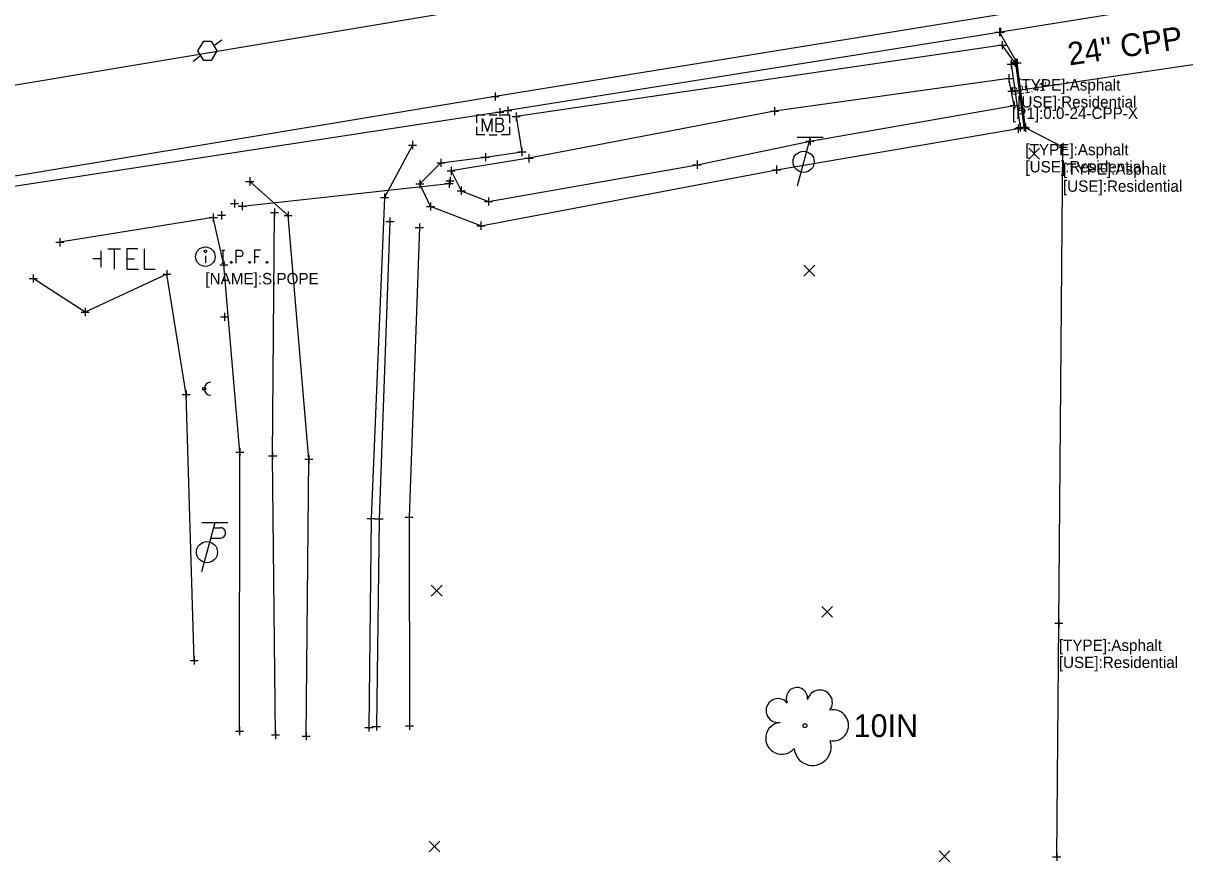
# Model space of a CAD drawing. Extents: x 1386013 to 1389776, y 604170 to 607009.
# Drawn here: x 1386419.5 to 1386562.3, y 604550 to 604653.1 of the extents above; entities that cross this region are included whole.
import ezdxf

# ---------------------------------------------------------------- set-up
doc = ezdxf.new("R2010")
doc.units = 0
for name, color, linetype in [('_CIVIL_CONSTRUCTION', 7, 'Continuous'), ('Default', 7, 'Continuous'), ('DR_X_Ditch', 7, 'Continuous'), ('DR_X_Elev_Flow', 7, 'Continuous'), ('DR_X_Headwall', 7, 'Continuous'), ('DR_X_Storm_Sewer', 7, 'Continuous'), ('DR_X_Text', 7, 'Continuous'), ('DV_X_Text', 7, 'Continuous'), ('PV_X_COP', 7, 'Continuous'), ('PV_X_Driveway', 7, 'Continuous'), ('PV_X_EOP', 7, 'Continuous'), ('PV_X_Shoulder', 7, 'Continuous'), ('RD_X_Cells', 7, 'Continuous'), ('RW_P_Esmt_SH', 7, 'Continuous'), ('SC_Scratch1', 7, 'Continuous'), ('SV_P_Mon_Cells_Set', 7, 'Continuous'), ('SV_X_Mon_Cells_Found_Text', 7, 'Continuous'), ('SV_X_Random_Point', 7, 'Continuous'), ('SV_X_Text', 7, 'Continuous'), ('SV_X_Toe_of_Slope', 7, 'Continuous'), ('SV_X_Top_of_Bank', 7, 'Continuous'), ('UT_X_Telecom_Cells', 7, 'Continuous'), ('VG_X_Text', 7, 'Continuous')]:
    doc.layers.add(name, color=color, linetype=linetype)

msp = doc.modelspace()

# ---------------------------------------------------------------- linework, layer by layer
at = {"layer": '_CIVIL_CONSTRUCTION'}
msp.add_circle((1386515.61, 604566.7), 0.24, dxfattribs=at)
for centre, radius, start, end in [((1386514.63, 604570.07), 1.32, 354.0047, 205.9741), ((1386517.44, 604569.53), 1.55, 323.83, 165.0376), ((1386512.3, 604568.56), 1.47, 39.0625, 279.5412), ((1386519.07, 604566.74), 1.91, 259.1453, 101.4596), ((1386512.76, 604565.15), 1.97, 96.1722, 320.5737), ((1386516.56, 604564.09), 2.28, 184.9476, 19.4572)]:
    msp.add_arc(centre, radius, start, end, dxfattribs=at)
at = {"layer": 'Default'}
msp.add_lwpolyline([(1386446.4, 604630.59), (1386471.84, 604633.36)], dxfattribs=at)
at = {"layer": 'DR_X_Ditch'}
msp.add_lwpolyline([(1386446.07, 604566.04), (1386446.11, 604600.33), (1386444.14, 604623.38), (1386442.84, 604629.19), (1386423.97, 604626.15)], dxfattribs=at)
at = {"layer": 'DR_X_Elev_Flow'}
for p, q in [((1386471.46, 604633.71), (1386472.46, 604633.71)), ((1386471.96, 604634.21), (1386471.96, 604633.21)), ((1386471.96, 604633.71), (1386471.96, 604633.71)), ((1386444.95, 604630.92), (1386445.95, 604630.92)), ((1386445.45, 604631.42), (1386445.45, 604630.42)), ((1386445.45, 604630.92), (1386445.45, 604630.92)), ((1386443.36, 604629.47), (1386444.36, 604629.47)), ((1386443.86, 604629.97), (1386443.86, 604628.97)), ((1386443.86, 604629.47), (1386443.86, 604629.47)), ((1386443.72, 604616.97), (1386444.72, 604616.97)), ((1386444.22, 604617.47), (1386444.22, 604616.47)), ((1386444.22, 604616.97), (1386444.22, 604616.97))]:
    msp.add_line(p, q, dxfattribs=at)
at = {"layer": 'DR_X_Headwall'}
msp.add_lwpolyline([(1386541.55, 604648.22), (1386540.98, 604648.07), (1386542.07, 604640.28), (1386542.59, 604640.31)], close=True, dxfattribs=at)
at = {"layer": 'DR_X_Storm_Sewer'}
for q in [(1386569.43, 604648.91), (1386541.08, 604644.72)]:
    msp.add_line((1386541.08, 604644.72), q, dxfattribs=at)
at = {"layer": 'DV_X_Text'}
for p, q in [((1386539.06, 604652.01), (1386540.06, 604652.01)), ((1386539.17, 604652.01), (1386540.17, 604652.01)), ((1386539.56, 604652.51), (1386539.56, 604651.51)), ((1386539.56, 604652.01), (1386539.56, 604652.01)), ((1386539.67, 604652.51), (1386539.67, 604651.51)), ((1386539.67, 604652.01), (1386539.67, 604652.01)), ((1386539.86, 604650.89), (1386539.86, 604649.89)), ((1386539.36, 604650.39), (1386540.36, 604650.39)), ((1386539.86, 604650.39), (1386539.86, 604650.39)), ((1386540.48, 604648.07), (1386541.48, 604648.07)), ((1386540.91, 604648.25), (1386541.91, 604648.25)), ((1386540.98, 604648.57), (1386540.98, 604647.57)), ((1386540.98, 604648.07), (1386540.98, 604648.07)), ((1386541.05, 604648.22), (1386542.05, 604648.22)), ((1386541.22, 604648.21), (1386542.22, 604648.21)), ((1386541.41, 604648.75), (1386541.41, 604647.75)), ((1386541.41, 604648.25), (1386541.41, 604648.25)), ((1386541.55, 604648.72), (1386541.55, 604647.72)), ((1386541.55, 604648.22), (1386541.55, 604648.22)), ((1386541.72, 604648.71), (1386541.72, 604647.71)), ((1386541.72, 604648.21), (1386541.72, 604648.21)), ((1386540.21, 604646.31), (1386541.21, 604646.31)), ((1386540.71, 604646.81), (1386540.71, 604645.81)), ((1386540.71, 604646.31), (1386540.71, 604646.31)), ((1386541.08, 604645.22), (1386541.08, 604644.22)), ((1386477.01, 604644.07), (1386478.01, 604644.07)), ((1386477.51, 604644.57), (1386477.51, 604643.57)), ((1386477.51, 604644.07), (1386477.51, 604644.07)), ((1386540.58, 604644.72), (1386541.58, 604644.72)), ((1386541.08, 604644.72), (1386541.08, 604644.72)), ((1386541.34, 604643.46), (1386541.34, 604642.46)), ((1386477.57, 604642.14), (1386478.57, 604642.14)), ((1386478.07, 604642.64), (1386478.07, 604641.64)), ((1386478.07, 604642.14), (1386478.07, 604642.14)), ((1386478.58, 604642.34), (1386479.58, 604642.34)), ((1386479.08, 604642.84), (1386479.08, 604641.84)), ((1386479.08, 604642.34), (1386479.08, 604642.34)), ((1386480.09, 604642.1), (1386480.09, 604641.1)), ((1386511.36, 604642.27), (1386512.36, 604642.27)), ((1386511.86, 604642.77), (1386511.86, 604641.77)), ((1386511.86, 604642.27), (1386511.86, 604642.27)), ((1386540.84, 604642.96), (1386541.84, 604642.96)), ((1386541.34, 604642.96), (1386541.34, 604642.96)), ((1386479.59, 604641.6), (1386480.59, 604641.6)), ((1386480.09, 604641.6), (1386480.09, 604641.6)), ((1386541.86, 604640.63), (1386541.86, 604639.63)), ((1386542.07, 604640.78), (1386542.07, 604639.78)), ((1386542.59, 604640.81), (1386542.59, 604639.81)), ((1386542.73, 604640.74), (1386542.73, 604639.74)), ((1386516.24, 604639.08), (1386516.24, 604638.08)), ((1386541.36, 604640.13), (1386542.36, 604640.13)), ((1386541.57, 604640.28), (1386542.57, 604640.28)), ((1386541.86, 604640.13), (1386541.86, 604640.13)), ((1386542.07, 604640.28), (1386542.07, 604640.28)), ((1386542.09, 604640.31), (1386543.09, 604640.31)), ((1386542.23, 604640.24), (1386543.23, 604640.24)), ((1386542.59, 604640.31), (1386542.59, 604640.31)), ((1386542.73, 604640.24), (1386542.73, 604640.24)), ((1386466.85, 604638.11), (1386467.85, 604638.11)), ((1386467.35, 604638.61), (1386467.35, 604637.61)), ((1386467.35, 604638.11), (1386467.35, 604638.11)), ((1386480.81, 604637.76), (1386480.81, 604636.76)), ((1386515.74, 604638.58), (1386516.74, 604638.58)), ((1386516.24, 604638.58), (1386516.24, 604638.58)), ((1386546.85, 604637.86), (1386547.85, 604637.86)), ((1386547.35, 604638.36), (1386547.35, 604637.36)), ((1386547.35, 604637.86), (1386547.35, 604637.86)), ((1386470.84, 604636.42), (1386470.84, 604635.42)), ((1386475.81, 604636.61), (1386476.81, 604636.61)), ((1386476.31, 604637.11), (1386476.31, 604636.11)), ((1386476.31, 604636.61), (1386476.31, 604636.61)), ((1386480.31, 604637.26), (1386481.31, 604637.26)), ((1386480.81, 604637.26), (1386480.81, 604637.26)), ((1386481.17, 604636.48), (1386482.17, 604636.48)), ((1386481.67, 604636.98), (1386481.67, 604635.98)), ((1386481.67, 604636.48), (1386481.67, 604636.48)), ((1386502.34, 604636.19), (1386502.34, 604635.19)), ((1386470.34, 604635.92), (1386471.34, 604635.92)), ((1386470.84, 604635.92), (1386470.84, 604635.92)), ((1386471.6, 604634.92), (1386472.6, 604634.92)), ((1386472.1, 604635.42), (1386472.1, 604634.42)), ((1386472.1, 604634.92), (1386472.1, 604634.92)), ((1386501.84, 604635.69), (1386502.84, 604635.69)), ((1386502.34, 604635.69), (1386502.34, 604635.69)), ((1386511.63, 604635.08), (1386512.63, 604635.08)), ((1386512.13, 604635.58), (1386512.13, 604634.58)), ((1386512.13, 604635.08), (1386512.13, 604635.08)), ((1386446.82, 604633.64), (1386447.82, 604633.64)), ((1386447.32, 604634.14), (1386447.32, 604633.14)), ((1386447.32, 604633.64), (1386447.32, 604633.64)), ((1386467.75, 604633.32), (1386468.75, 604633.32)), ((1386468.25, 604633.82), (1386468.25, 604632.82)), ((1386468.25, 604633.32), (1386468.25, 604633.32)), ((1386471.34, 604633.36), (1386472.34, 604633.36)), ((1386471.84, 604633.86), (1386471.84, 604632.86)), ((1386471.84, 604633.36), (1386471.84, 604633.36)), ((1386463.89, 604632.16), (1386463.89, 604631.16)), ((1386472.85, 604632.49), (1386473.85, 604632.49)), ((1386473.35, 604632.99), (1386473.35, 604631.99)), ((1386473.35, 604632.49), (1386473.35, 604632.49)), ((1386445.9, 604630.59), (1386446.9, 604630.59)), ((1386446.4, 604631.09), (1386446.4, 604630.09)), ((1386446.4, 604630.59), (1386446.4, 604630.59)), ((1386463.39, 604631.66), (1386464.39, 604631.66)), ((1386463.89, 604631.66), (1386463.89, 604631.66)), ((1386469.07, 604630.56), (1386470.07, 604630.56)), ((1386469.57, 604631.06), (1386469.57, 604630.06)), ((1386469.57, 604630.56), (1386469.57, 604630.56)), ((1386476.18, 604631.17), (1386477.18, 604631.17)), ((1386476.68, 604631.67), (1386476.68, 604630.67)), ((1386476.68, 604631.17), (1386476.68, 604631.17)), ((1386442.34, 604629.19), (1386443.34, 604629.19)), ((1386442.84, 604629.69), (1386442.84, 604628.69)), ((1386442.84, 604629.19), (1386442.84, 604629.19)), ((1386449.88, 604629.82), (1386450.88, 604629.82)), ((1386450.38, 604630.32), (1386450.38, 604629.32)), ((1386450.38, 604629.82), (1386450.38, 604629.82)), ((1386451.55, 604629.43), (1386452.55, 604629.43)), ((1386452.05, 604629.93), (1386452.05, 604628.93)), ((1386452.05, 604629.43), (1386452.05, 604629.43)), ((1386464.57, 604629.2), (1386464.57, 604628.2)), ((1386464.07, 604628.7), (1386465.07, 604628.7)), ((1386464.57, 604628.7), (1386464.57, 604628.7)), ((1386467.69, 604627.97), (1386468.69, 604627.97)), ((1386468.19, 604628.47), (1386468.19, 604627.47)), ((1386468.19, 604627.97), (1386468.19, 604627.97)), ((1386475.24, 604628.19), (1386476.24, 604628.19)), ((1386475.74, 604628.69), (1386475.74, 604627.69)), ((1386475.74, 604628.19), (1386475.74, 604628.19)), ((1386423.97, 604626.65), (1386423.97, 604625.65)), ((1386423.47, 604626.15), (1386424.47, 604626.15)), ((1386423.97, 604626.15), (1386423.97, 604626.15)), ((1386443.64, 604623.38), (1386444.64, 604623.38)), ((1386444.14, 604623.88), (1386444.14, 604622.88)), ((1386444.14, 604623.38), (1386444.14, 604623.38)), ((1386420.7, 604622.2), (1386420.7, 604621.2)), ((1386436.63, 604622.24), (1386437.63, 604622.24)), ((1386437.13, 604622.74), (1386437.13, 604621.74)), ((1386437.13, 604622.24), (1386437.13, 604622.24)), ((1386420.2, 604621.7), (1386421.2, 604621.7)), ((1386420.7, 604621.7), (1386420.7, 604621.7)), ((1386427.08, 604618.07), (1386427.08, 604617.07)), ((1386426.58, 604617.57), (1386427.58, 604617.57)), ((1386427.08, 604617.57), (1386427.08, 604617.57)), ((1386439.5, 604607.92), (1386439.5, 604606.92)), ((1386439, 604607.42), (1386440, 604607.42)), ((1386439.5, 604607.42), (1386439.5, 604607.42)), ((1386446.11, 604600.83), (1386446.11, 604599.83)), ((1386445.61, 604600.33), (1386446.61, 604600.33)), ((1386446.11, 604600.33), (1386446.11, 604600.33)), ((1386449.64, 604599.89), (1386450.64, 604599.89)), ((1386450.14, 604600.39), (1386450.14, 604599.39)), ((1386450.14, 604599.89), (1386450.14, 604599.89)), ((1386454.09, 604599.46), (1386455.09, 604599.46)), ((1386454.59, 604599.96), (1386454.59, 604598.96)), ((1386454.59, 604599.46), (1386454.59, 604599.46)), ((1386461.76, 604592.18), (1386462.76, 604592.18)), ((1386462.26, 604592.68), (1386462.26, 604591.68)), ((1386462.26, 604592.18), (1386462.26, 604592.18)), ((1386462.74, 604592.13), (1386463.74, 604592.13)), ((1386463.24, 604592.63), (1386463.24, 604591.63)), ((1386463.24, 604592.13), (1386463.24, 604592.13)), ((1386466.43, 604592.36), (1386467.43, 604592.36)), ((1386466.93, 604592.86), (1386466.93, 604591.86)), ((1386466.93, 604592.36), (1386466.93, 604592.36)), ((1386546.34, 604579.29), (1386547.34, 604579.29)), ((1386546.84, 604579.79), (1386546.84, 604578.79)), ((1386546.84, 604579.29), (1386546.84, 604579.29)), ((1386440.49, 604575.23), (1386440.49, 604574.23)), ((1386439.99, 604574.73), (1386440.99, 604574.73)), ((1386440.49, 604574.73), (1386440.49, 604574.73)), ((1386446.07, 604566.54), (1386446.07, 604565.54)), ((1386461.49, 604566.49), (1386462.49, 604566.49)), ((1386461.99, 604566.99), (1386461.99, 604565.99)), ((1386461.99, 604566.49), (1386461.99, 604566.49)), ((1386462.4, 604566.6), (1386463.4, 604566.6)), ((1386462.9, 604567.1), (1386462.9, 604566.1)), ((1386462.9, 604566.6), (1386462.9, 604566.6)), ((1386466.47, 604566.67), (1386467.47, 604566.67)), ((1386466.97, 604567.17), (1386466.97, 604566.17)), ((1386466.97, 604566.67), (1386466.97, 604566.67)), ((1386445.57, 604566.04), (1386446.57, 604566.04)), ((1386446.07, 604566.04), (1386446.07, 604566.04)), ((1386449.99, 604565.56), (1386450.99, 604565.56)), ((1386450.49, 604566.06), (1386450.49, 604565.06)), ((1386450.49, 604565.56), (1386450.49, 604565.56)), ((1386453.77, 604565.4), (1386454.77, 604565.4)), ((1386454.27, 604565.9), (1386454.27, 604564.9)), ((1386454.27, 604565.4), (1386454.27, 604565.4)), ((1386546.08, 604550.58), (1386547.08, 604550.58)), ((1386546.58, 604551.08), (1386546.58, 604550.08)), ((1386546.58, 604550.58), (1386546.58, 604550.58))]:
    msp.add_line(p, q, dxfattribs=at)
at = {"layer": 'PV_X_COP'}
msp.add_lwpolyline([(1387000.37, 604739.9), (1386941.92, 604730.57), (1386886.1, 604721.12), (1386828.75, 604712.1), (1386771.72, 604702.67), (1386713.85, 604693.61), (1386656.33, 604684.46), (1386594.48, 604674.79), (1386537.3, 604664.92), (1386475.24, 604654.93), (1386414.35, 604644.79), (1386366.58, 604636.8), (1386295.22, 604625.24), (1386269.2, 604620.76)], dxfattribs=at)
at = {"layer": 'PV_X_Driveway'}
for points in [[(1386546.58, 604550.58), (1386546.84, 604579.29), (1386547.35, 604637.86), (1386542.73, 604640.24), (1386541.72, 604648.21), (1386539.56, 604652.01)], [(1386467.35, 604638.11), (1386463.89, 604631.66), (1386462.26, 604592.18), (1386461.99, 604566.49)], [(1386454.27, 604565.4), (1386454.59, 604599.46), (1386452.05, 604629.43), (1386447.32, 604633.64)]]:
    msp.add_lwpolyline(points, dxfattribs=at)
at = {"layer": 'PV_X_EOP'}
msp.add_lwpolyline([(1387002.9, 604729.17), (1386943.42, 604719.4), (1386887.14, 604710.13), (1386830.12, 604700.78), (1386772.1, 604691.69), (1386715.3, 604682.94), (1386657.65, 604673.44), (1386596.41, 604663.71), (1386538.98, 604654.04), (1386477.51, 604644.07), (1386414.44, 604633.64), (1386368.83, 604626.04), (1386296.84, 604614.17), (1386270.69, 604609.87)], dxfattribs=at)
at = {"layer": 'PV_X_Shoulder'}
msp.add_lwpolyline([(1386985.4, 604722.84), (1386965.11, 604719.46), (1386961.9, 604720.55), (1386943.38, 604718.17), (1386887.62, 604708.36), (1386830.36, 604699.21), (1386772.3, 604689.74), (1386715.56, 604681.18), (1386657.89, 604671.95), (1386596.66, 604661.6), (1386577.12, 604657.52), (1386569.07, 604656.76), (1386539.67, 604652.01), (1386479.08, 604642.34), (1386478.07, 604642.14), (1386414.53, 604632.43), (1386369.38, 604624.9), (1386296.82, 604613.19), (1386270.73, 604608.85)], dxfattribs=at)
at = {"layer": 'RD_X_Cells'}
for p, q in [((1386476.76, 604641.81), (1386477.76, 604641.81)), ((1386477.27, 604640.59), (1386477.27, 604640.59)), ((1386476.76, 604639.37), (1386477.76, 604639.37))]:
    msp.add_line(p, q, dxfattribs=at)
for points in [[(1386475.27, 604640.84), (1386475.27, 604641.81), (1386476.24, 604641.81)], [(1386475.97, 604639.79), (1386475.97, 604641.39), (1386476.55, 604639.79), (1386477.11, 604641.39), (1386477.11, 604639.79)], [(1386478.29, 604640.66), (1386478.36, 604640.72), (1386478.39, 604640.76), (1386478.42, 604640.8), (1386478.43, 604640.82), (1386478.46, 604640.87), (1386478.47, 604640.91), (1386478.49, 604641), (1386478.49, 604641.04), (1386478.49, 604641.09), (1386478.48, 604641.16), (1386478.46, 604641.23), (1386478.42, 604641.28), (1386478.36, 604641.33), (1386478.31, 604641.35), (1386478.28, 604641.37), (1386478.22, 604641.39), (1386477.6, 604641.39), (1386477.6, 604639.79), (1386478.29, 604639.79), (1386478.38, 604639.84), (1386478.46, 604639.9), (1386478.52, 604640.01), (1386478.56, 604640.12), (1386478.57, 604640.23), (1386478.57, 604640.31), (1386478.54, 604640.38), (1386478.49, 604640.5), (1386478.43, 604640.57), (1386478.29, 604640.66), (1386477.6, 604640.66)], [(1386478.28, 604641.81), (1386479.27, 604641.81), (1386479.27, 604640.84)], [(1386476.24, 604639.37), (1386475.27, 604639.37), (1386475.27, 604640.34)], [(1386479.27, 604640.34), (1386479.27, 604639.37), (1386478.28, 604639.37)]]:
    msp.add_lwpolyline(points, dxfattribs=at)
at = {"layer": 'RW_P_Esmt_SH'}
for p, q in [((1386443.88, 604651.02), (1386442.92, 604650.3)), ((1386441.31, 604649.1), (1386440.35, 604648.38))]:
    msp.add_line(p, q, dxfattribs=at)
msp.add_lwpolyline([(1386441.66, 604650.9), (1386442.56, 604650.9), (1386443.27, 604649.7), (1386442.56, 604648.5), (1386441.66, 604648.5), (1386440.95, 604649.7)], close=True, dxfattribs=at)
at = {"layer": 'SC_Scratch1'}
msp.add_line((1386441.87, 604624.5), (1386441.87, 604623.61), dxfattribs=at)
for points in [[(1386443.9, 604625.18), (1386444.25, 604625.18)], [(1386444.07, 604623.58), (1386444.07, 604625.18)], [(1386445.64, 604623.58), (1386445.64, 604625.18), (1386446.17, 604625.18), (1386446.22, 604625.17), (1386446.3, 604625.14), (1386446.33, 604625.12), (1386446.37, 604625.09), (1386446.41, 604625.03), (1386446.44, 604624.96), (1386446.47, 604624.86), (1386446.47, 604624.71), (1386446.45, 604624.66), (1386446.43, 604624.59), (1386446.39, 604624.5), (1386446.34, 604624.46), (1386446.31, 604624.44), (1386446.26, 604624.41), (1386446.17, 604624.4), (1386445.64, 604624.4)], [(1386448.65, 604625.18), (1386447.89, 604625.18), (1386447.89, 604623.58)], [(1386443.9, 604623.58), (1386444.25, 604623.58)], [(1386445.03, 604623.79), (1386445.09, 604623.79), (1386445.12, 604623.77), (1386445.15, 604623.72), (1386445.15, 604623.65), (1386445.12, 604623.6), (1386445.09, 604623.58), (1386445.03, 604623.58), (1386445, 604623.6), (1386444.97, 604623.65), (1386444.97, 604623.72), (1386445, 604623.77), (1386445.03, 604623.79)], [(1386447.28, 604623.79), (1386447.34, 604623.79), (1386447.37, 604623.77), (1386447.4, 604623.72), (1386447.4, 604623.65), (1386447.37, 604623.6), (1386447.34, 604623.58), (1386447.28, 604623.58), (1386447.25, 604623.6), (1386447.22, 604623.65), (1386447.22, 604623.72), (1386447.25, 604623.77), (1386447.28, 604623.79)], [(1386447.89, 604624.4), (1386448.43, 604624.4)], [(1386449.43, 604623.79), (1386449.49, 604623.79), (1386449.52, 604623.77), (1386449.55, 604623.72), (1386449.55, 604623.65), (1386449.52, 604623.6), (1386449.49, 604623.58), (1386449.43, 604623.58), (1386449.4, 604623.6), (1386449.36, 604623.65), (1386449.36, 604623.72), (1386449.4, 604623.77), (1386449.43, 604623.79)]]:
    msp.add_lwpolyline(points, dxfattribs=at)
for centre, radius in [((1386441.87, 604624.38), 1.2), ((1386441.87, 604625.03), 0.16)]:
    msp.add_circle(centre, radius, dxfattribs=at)
at = {"layer": 'SV_P_Mon_Cells_Set'}
for p, q in [((1386443.02, 604591.64), (1386441.41, 604585.64)), ((1386444.62, 604591.64), (1386441.42, 604591.64)), ((1386442.86, 604591.04), (1386443.71, 604591.04)), ((1386442.52, 604589.77), (1386443.71, 604589.77))]:
    msp.add_line(p, q, dxfattribs=at)
for centre, radius in [((1386441.72, 604608.13), 0.2), ((1386442.06, 604588.04), 1.3)]:
    msp.add_circle(centre, radius, dxfattribs=at)
for centre, radius, start, end in [((1386442.52, 604608.13), 0.8, 90, 270), ((1386443.72, 604590.41), 0.638, 268.8767, 91.1233)]:
    msp.add_arc(centre, radius, start, end, dxfattribs=at)
at = {"layer": 'SV_X_Random_Point'}
for p, q in [((1386543.14, 604636.38), (1386544.48, 604637.71)), ((1386543.14, 604637.71), (1386544.48, 604636.38)), ((1386515.49, 604622), (1386516.82, 604623.34)), ((1386515.49, 604623.34), (1386516.82, 604622)), ((1386469.66, 604582.64), (1386471, 604583.98)), ((1386469.66, 604583.98), (1386471, 604582.64)), ((1386517.68, 604580.03), (1386519.01, 604581.36)), ((1386517.68, 604581.36), (1386519.01, 604580.03)), ((1386469.38, 604551.18), (1386470.72, 604552.51)), ((1386469.38, 604552.51), (1386470.72, 604551.18)), ((1386532.12, 604549.96), (1386533.45, 604551.3)), ((1386532.12, 604551.3), (1386533.45, 604549.96))]:
    msp.add_line(p, q, dxfattribs=at)
at = {"layer": 'SV_X_Toe_of_Slope'}
msp.add_lwpolyline([(1386540.71, 604646.31), (1386511.86, 604642.27), (1386481.67, 604636.48), (1386472.1, 604634.92), (1386473.35, 604632.49), (1386476.68, 604631.17), (1386502.34, 604635.69), (1386516.24, 604638.58), (1386541.34, 604642.96)], close=True, dxfattribs=at)
msp.add_lwpolyline([(1386468.19, 604627.97), (1386466.93, 604592.36), (1386466.97, 604566.67)], dxfattribs=at)
at = {"layer": 'SV_X_Top_of_Bank'}
for points in [[(1386541.41, 604648.25), (1386539.86, 604650.39), (1386480.09, 604641.6), (1386480.81, 604637.26)], [(1386475.74, 604628.19), (1386512.13, 604635.08), (1386541.86, 604640.13)], [(1386475.74, 604628.19), (1386469.57, 604630.56), (1386468.25, 604633.32), (1386470.84, 604635.92), (1386476.31, 604636.61), (1386480.81, 604637.26)], [(1386450.49, 604565.56), (1386450.14, 604599.89), (1386450.38, 604629.82)], [(1386464.57, 604628.7), (1386463.24, 604592.13), (1386462.9, 604566.6)], [(1386440.49, 604574.73), (1386439.5, 604607.42), (1386437.13, 604622.24), (1386427.08, 604617.57), (1386420.7, 604621.7)]]:
    msp.add_lwpolyline(points, dxfattribs=at)
at = {"layer": 'UT_X_Telecom_Cells'}
for p, q in [((1386516.25, 604639.05), (1386514.64, 604633.05)), ((1386517.85, 604639.05), (1386514.65, 604639.05)), ((1386429.04, 604623.1), (1386429.04, 604625.1)), ((1386429.04, 604624.1), (1386428.04, 604624.1))]:
    msp.add_line(p, q, dxfattribs=at)
for points in [[(1386429.85, 604625.34), (1386431.41, 604625.34)], [(1386430.64, 604625.34), (1386430.64, 604622.84)], [(1386433.55, 604625.34), (1386432.19, 604625.34), (1386432.19, 604622.84), (1386433.65, 604622.84)], [(1386434.34, 604625.34), (1386434.34, 604622.84), (1386435.7, 604622.84)], [(1386432.19, 604624.1), (1386433.16, 604624.1)]]:
    msp.add_lwpolyline(points, dxfattribs=at)
msp.add_circle((1386515.45, 604636.05), 1.3, dxfattribs=at)

# ---------------------------------------------------------------- texts
at = {"layer": 'DR_X_Text'}
msp.add_text('24" CPP', height=2.8, rotation=8.4033, dxfattribs=at).set_placement((1386548.14, 604647.89))
at = {"layer": 'SC_Scratch1'}
msp.add_text("921.41'", height=1, rotation=8.4033, dxfattribs=at).set_placement((1386541.16, 604644.23))
at = {"layer": 'SV_X_Mon_Cells_Found_Text'}
msp.add_text('[NAME]:S.POPE', height=1.4, dxfattribs=at).set_placement((1386441.87, 604620.98))
at = {"layer": 'SV_X_Text'}
for s, p in [('[TYPE]:Asphalt', (1386541.72, 604644.81)), ('[USE]:Residential', (1386541.72, 604642.71)), ('[P1]:0.0-24-CPP-X', (1386541.08, 604641.32)), ('[TYPE]:Asphalt', (1386542.73, 604636.84)), ('[USE]:Residential', (1386542.73, 604634.74)), ('[TYPE]:Asphalt', (1386547.35, 604634.46)), ('[USE]:Residential', (1386547.35, 604632.36)), ('[TYPE]:Asphalt', (1386546.84, 604575.89)), ('[USE]:Residential', (1386546.84, 604573.79))]:
    msp.add_text(s, height=1.4, dxfattribs=at).set_placement(p)
at = {"layer": 'VG_X_Text'}
msp.add_text('10IN', height=2.8, dxfattribs=at).set_placement((1386521.61, 604565.3))

doc.saveas('drawing.dxf')
